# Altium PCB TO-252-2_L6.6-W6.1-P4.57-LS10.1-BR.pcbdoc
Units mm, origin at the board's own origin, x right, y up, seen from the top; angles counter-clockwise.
Board outline 24.63 x 20.07 mm, 2 copper layers (Top Layer, Bottom Layer), stack 0 mm thick; 1 components, 0 nets, 3 pads, 0 vias.
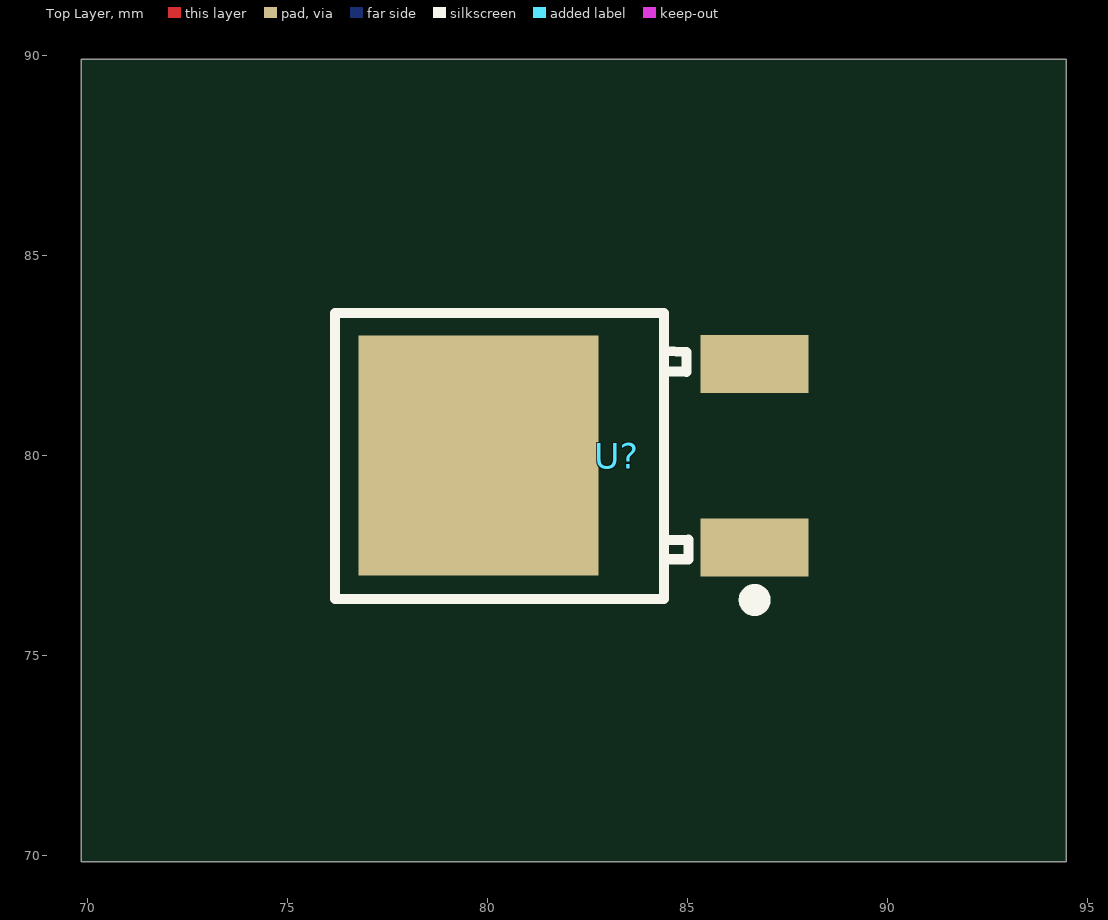
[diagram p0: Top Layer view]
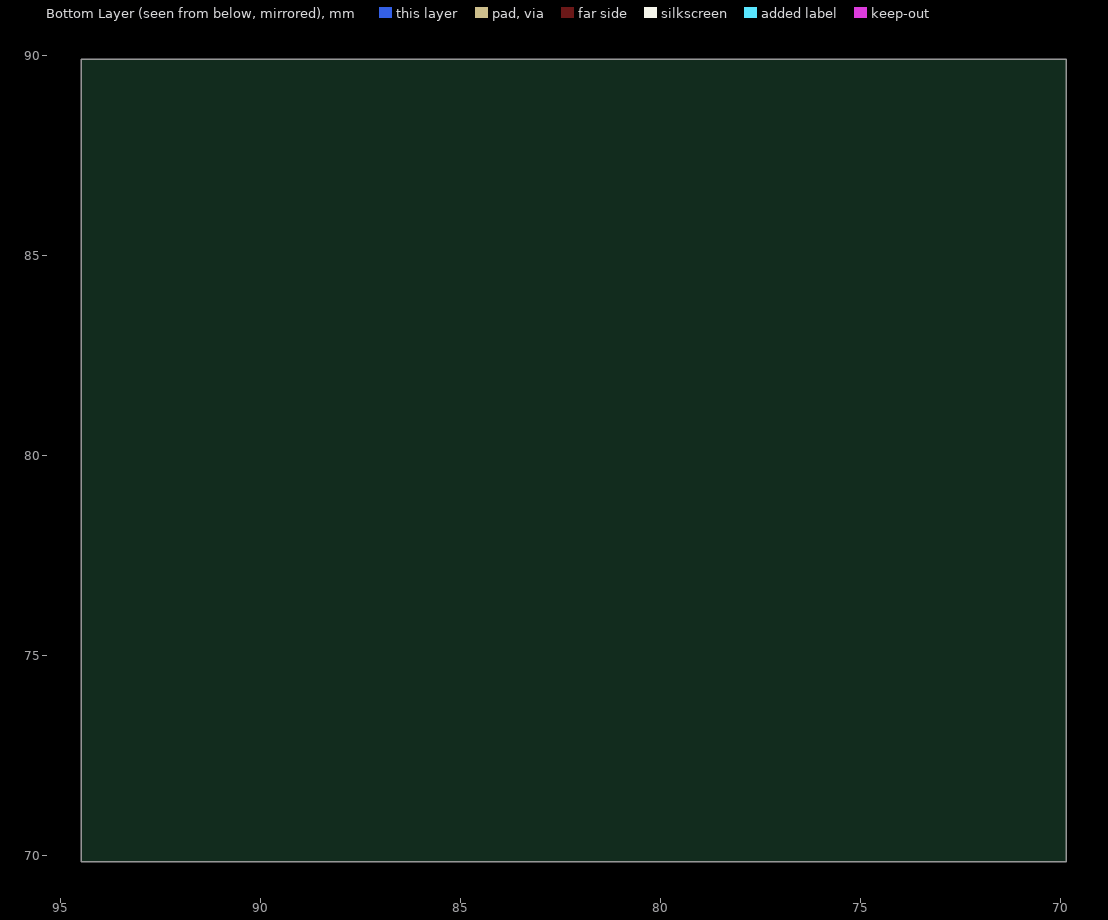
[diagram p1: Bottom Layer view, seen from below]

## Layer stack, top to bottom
Top Layer: signal copper (thickness not stored)
Bottom Layer: signal copper (thickness not stored)

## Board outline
94.483,69.85 69.85,69.85 69.85,89.921 94.483,89.921

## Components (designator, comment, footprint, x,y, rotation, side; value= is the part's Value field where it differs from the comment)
U? "" TO-252-2_L6.6-W6.1-P4.57-LS10.1-BR 83.235,80.007 r0 top

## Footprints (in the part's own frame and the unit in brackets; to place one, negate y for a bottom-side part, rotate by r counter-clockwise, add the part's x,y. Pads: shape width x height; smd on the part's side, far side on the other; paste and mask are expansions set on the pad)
TO-252-2_L6.6-W6.1-P4.57-LS10.1-BR [mm]
  rect 2.7x1.45 smd: 1(3.45,-2.29) 3(3.45,2.29)
  rect 6x6 smd: 2(-3.45,0)
  silkscreen extent -7.04,-3.81 3.66,3.56

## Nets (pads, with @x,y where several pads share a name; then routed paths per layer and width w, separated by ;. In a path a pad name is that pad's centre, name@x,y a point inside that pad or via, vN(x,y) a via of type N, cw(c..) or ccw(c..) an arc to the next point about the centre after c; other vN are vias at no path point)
pads on no net: U?.1 U?.2 U?.3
